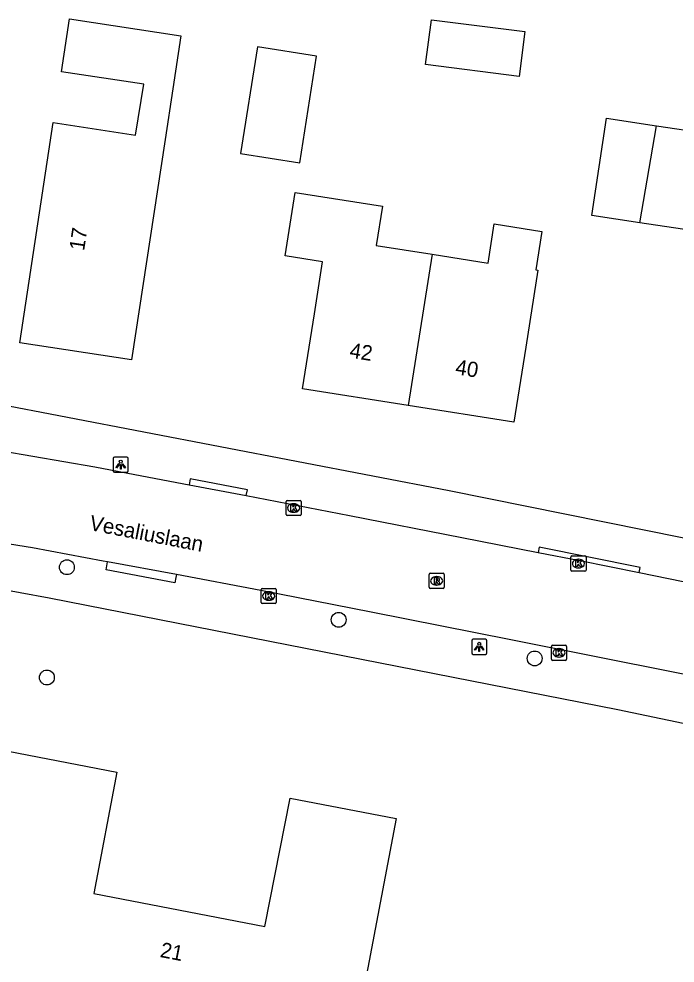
# Model space of a CAD drawing. Extents: x 161486 to 162249, y 379484 to 380829.
# Drawn here: x 161831.1 to 161874.4, y 380395.2 to 380457.4 of the extents above; entities that cross this region are included whole.
import ezdxf

# ---------------------------------------------------------------- set-up
doc = ezdxf.new("R2010")
doc.units = 0
for name, color, linetype in [('IMGEO_Boom', 7, 'Continuous'), ('IMGEO_Kolk', 7, 'Continuous'), ('IMGEO_Lichtpunt', 7, 'Continuous'), ('IMGEO_Openbare_ruimte_label', 7, 'Continuous'), ('IMGEO_Pand', 7, 'Continuous'), ('IMGEO_Pand_nummerreeks', 7, 'Continuous'), ('IMGEO_Rijbaan_lokaal_open', 7, 'Continuous'), ('IMGEO_Rioolput', 7, 'Continuous'), ('IMGEO_Voetpad_open', 7, 'Continuous')]:
    doc.layers.add(name, color=color, linetype=linetype)

msp = doc.modelspace()

# ---------------------------------------------------------------- linework, layer by layer
at = {"layer": 'IMGEO_Boom'}
for centre in [(161834.306, 380421.314), (161852.217, 380417.851), (161865.132, 380415.308), (161832.988, 380414.053)]:
    msp.add_circle(centre, 0.489, dxfattribs=at)
at = {"layer": 'IMGEO_Kolk'}
for p, q in [((161848.821, 380425.714), (161849.673, 380425.714)), ((161848.746, 380424.788), (161848.746, 380425.64)), ((161849.234, 380425.494), (161849.259, 380425.494)), ((161849.747, 380425.64), (161849.747, 380424.788)), ((161849.673, 380424.714), (161848.821, 380424.714)), ((161849.257, 380424.934), (161849.232, 380424.934)), ((161867.512, 380421.129), (161867.512, 380421.981)), ((161867.587, 380422.055), (161868.439, 380422.055)), ((161868.513, 380421.981), (161868.513, 380421.129)), ((161868, 380421.835), (161868.025, 380421.835)), ((161868.439, 380421.055), (161867.587, 380421.055)), ((161868.023, 380421.275), (161867.998, 380421.275)), ((161847.103, 380418.995), (161847.103, 380419.847)), ((161847.178, 380419.921), (161848.03, 380419.921)), ((161847.591, 380419.701), (161847.616, 380419.701)), ((161848.104, 380419.847), (161848.104, 380418.995)), ((161848.03, 380418.921), (161847.178, 380418.921)), ((161847.614, 380419.141), (161847.589, 380419.141)), ((161866.235, 380415.253), (161866.235, 380416.105)), ((161866.31, 380416.179), (161867.162, 380416.179)), ((161866.723, 380415.959), (161866.748, 380415.959)), ((161867.236, 380416.105), (161867.236, 380415.253)), ((161867.162, 380415.179), (161866.31, 380415.179)), ((161866.746, 380415.399), (161866.721, 380415.399))]:
    msp.add_line(p, q, dxfattribs=at)
for points in [[(161848.821, 380425.714), (161849.673, 380425.714)], [(161848.746, 380424.788), (161848.746, 380425.64)], [(161849.067, 380425.414), (161849.19, 380425.414), (161849.19, 380425.263), (161849.32, 380425.414), (161849.484, 380425.414), (161849.338, 380425.263), (161849.491, 380425.014), (161849.339, 380425.014), (161849.254, 380425.178), (161849.19, 380425.111), (161849.19, 380425.014), (161849.067, 380425.014), (161849.067, 380425.414)], [(161849.747, 380425.64), (161849.747, 380424.788)], [(161849.673, 380424.714), (161848.821, 380424.714)], [(161867.512, 380421.129), (161867.512, 380421.981)], [(161867.587, 380422.055), (161868.439, 380422.055)], [(161868.513, 380421.981), (161868.513, 380421.129)], [(161867.833, 380421.755), (161867.956, 380421.755), (161867.956, 380421.604), (161868.086, 380421.755), (161868.25, 380421.755), (161868.104, 380421.604), (161868.257, 380421.355), (161868.105, 380421.355), (161868.02, 380421.519), (161867.956, 380421.452), (161867.956, 380421.355), (161867.833, 380421.355), (161867.833, 380421.755)], [(161868.439, 380421.055), (161867.587, 380421.055)], [(161847.103, 380418.995), (161847.103, 380419.847)], [(161847.178, 380419.921), (161848.03, 380419.921)], [(161847.424, 380419.621), (161847.547, 380419.621), (161847.547, 380419.47), (161847.677, 380419.621), (161847.841, 380419.621), (161847.695, 380419.47), (161847.848, 380419.221), (161847.696, 380419.221), (161847.611, 380419.385), (161847.547, 380419.318), (161847.547, 380419.221), (161847.424, 380419.221), (161847.424, 380419.621)], [(161848.104, 380419.847), (161848.104, 380418.995)], [(161848.03, 380418.921), (161847.178, 380418.921)], [(161866.235, 380415.253), (161866.235, 380416.105)], [(161866.31, 380416.179), (161867.162, 380416.179)], [(161866.556, 380415.879), (161866.679, 380415.879), (161866.679, 380415.728), (161866.809, 380415.879), (161866.973, 380415.879), (161866.827, 380415.728), (161866.98, 380415.479), (161866.828, 380415.479), (161866.743, 380415.643), (161866.679, 380415.576), (161866.679, 380415.479), (161866.556, 380415.479), (161866.556, 380415.879)], [(161867.236, 380416.105), (161867.236, 380415.253)], [(161867.162, 380415.179), (161866.31, 380415.179)]]:
    msp.add_lwpolyline(points, dxfattribs=at)
for centre, start, end in [((161848.823, 380425.638), 91.55205, 178.44795), ((161848.823, 380425.638), 91.55205, 178.44795), ((161849.671, 380425.638), 1.55205, 88.44795), ((161849.671, 380425.638), 1.55205, 88.44795), ((161848.823, 380424.79), 181.55205, 268.44795), ((161848.823, 380424.79), 181.55205, 268.44795), ((161849.671, 380424.79), 271.55205, 358.44795), ((161849.671, 380424.79), 271.55205, 358.44795), ((161867.589, 380421.979), 91.55205, 178.44795), ((161867.589, 380421.979), 91.55205, 178.44795), ((161868.437, 380421.979), 1.55205, 88.44795), ((161868.437, 380421.979), 1.55205, 88.44795), ((161867.589, 380421.131), 181.55205, 268.44795), ((161867.589, 380421.131), 181.55205, 268.44795), ((161868.437, 380421.131), 271.55205, 358.44795), ((161868.437, 380421.131), 271.55205, 358.44795), ((161847.18, 380419.845), 91.55205, 178.44795), ((161847.18, 380419.845), 91.55205, 178.44795), ((161848.028, 380419.845), 1.55205, 88.44795), ((161848.028, 380419.845), 1.55205, 88.44795), ((161847.18, 380418.997), 181.55205, 268.44795), ((161847.18, 380418.997), 181.55205, 268.44795), ((161848.028, 380418.997), 271.55205, 358.44795), ((161848.028, 380418.997), 271.55205, 358.44795), ((161866.312, 380416.103), 91.55205, 178.44795), ((161866.312, 380416.103), 91.55205, 178.44795), ((161867.16, 380416.103), 1.55205, 88.44795), ((161867.16, 380416.103), 1.55205, 88.44795), ((161866.312, 380415.255), 181.55205, 268.44795), ((161866.312, 380415.255), 181.55205, 268.44795), ((161867.16, 380415.255), 271.55205, 358.44795), ((161867.16, 380415.255), 271.55205, 358.44795)]:
    msp.add_arc(centre, 0.0765, start, end, dxfattribs=at)
for centre, major_axis, ratio, start_param, end_param in [((161849.233, 380425.214), (-0.387, 0.002), 0.722429, 4.712389, 7.853982), ((161849.258, 380425.214), (-0.39, 0.002), 0.717154, 1.570796, 4.712389), ((161867.999, 380421.555), (-0.387, 0.002), 0.722429, 4.712389, 7.853982), ((161868.024, 380421.555), (-0.39, 0.002), 0.717154, 1.570796, 4.712389), ((161847.59, 380419.421), (-0.387, 0.002), 0.722429, 4.712389, 7.853982), ((161847.615, 380419.421), (-0.39, 0.002), 0.717154, 1.570796, 4.712389), ((161866.722, 380415.679), (-0.387, 0.002), 0.722429, 4.712389, 7.853982), ((161866.747, 380415.679), (-0.39, 0.002), 0.717154, 1.570796, 4.712389)]:
    msp.add_ellipse(centre, major_axis=major_axis, ratio=ratio, start_param=start_param, end_param=end_param, dxfattribs=at)
at = {"layer": 'IMGEO_Lichtpunt'}
for p, q in [((161837.358, 380428.471), (161837.358, 380427.664)), ((161837.358, 380428.471), (161837.358, 380427.664)), ((161838.26, 380428.566), (161837.452, 380428.566)), ((161838.26, 380428.566), (161837.452, 380428.566)), ((161838.354, 380427.664), (161838.354, 380428.471)), ((161838.354, 380427.664), (161838.354, 380428.471)), ((161837.452, 380427.57), (161838.26, 380427.57)), ((161837.452, 380427.57), (161838.26, 380427.57)), ((161860.98, 380416.476), (161860.98, 380415.669)), ((161860.98, 380416.476), (161860.98, 380415.669)), ((161861.882, 380416.571), (161861.074, 380416.571)), ((161861.882, 380416.571), (161861.074, 380416.571)), ((161861.976, 380415.669), (161861.976, 380416.476)), ((161861.976, 380415.669), (161861.976, 380416.476)), ((161861.074, 380415.575), (161861.882, 380415.575)), ((161861.074, 380415.575), (161861.882, 380415.575))]:
    msp.add_line(p, q, dxfattribs=at)
for points in [[(161837.732, 380428.135), (161837.771, 380428.107), (161837.583, 380427.845), (161837.545, 380427.872), (161837.732, 380428.135)], [(161837.944, 380428.107), (161837.982, 380428.134), (161838.169, 380427.872), (161838.13, 380427.844), (161837.944, 380428.107)], [(161837.834, 380428.087), (161837.881, 380428.087), (161837.881, 380427.765), (161837.834, 380427.765), (161837.834, 380428.087)], [(161861.354, 380416.14), (161861.393, 380416.112), (161861.205, 380415.85), (161861.167, 380415.877), (161861.354, 380416.14)], [(161861.456, 380416.092), (161861.503, 380416.092), (161861.503, 380415.77), (161861.456, 380415.77), (161861.456, 380416.092)], [(161861.566, 380416.112), (161861.604, 380416.139), (161861.791, 380415.877), (161861.752, 380415.849), (161861.566, 380416.112)]]:
    msp.add_lwpolyline(points, dxfattribs=at)
for centre in [(161837.857, 380428.269), (161861.479, 380416.274)]:
    msp.add_circle(centre, 0.0994, dxfattribs=at)
for centre, start, end in [((161837.452, 380428.471), 90, 180), ((161837.452, 380428.471), 90, 180), ((161838.26, 380428.471), 0, 90), ((161838.26, 380428.471), 0, 90), ((161837.452, 380427.664), 180, 270), ((161837.452, 380427.664), 180, 270), ((161838.26, 380427.664), 270, 0), ((161838.26, 380427.664), 270, 360), ((161861.074, 380416.476), 90, 180), ((161861.074, 380416.476), 90, 180), ((161861.882, 380416.476), 0, 90), ((161861.882, 380416.476), 0, 90), ((161861.074, 380415.669), 180, 270), ((161861.074, 380415.669), 180, 270), ((161861.882, 380415.669), 270, 0), ((161861.882, 380415.669), 270, 360)]:
    msp.add_arc(centre, 0.0946, start, end, dxfattribs=at)
at = {"layer": 'IMGEO_Pand'}
for points in [[(161841.285, 380452.827), (161840.776, 380449.476), (161838.573, 380434.968), (161831.208, 380436.086), (161833.411, 380450.594), (161838.839, 380449.771), (161839.386, 380453.116), (161833.958, 380453.939), (161834.487, 380457.423), (161841.814, 380456.311), (161841.285, 380452.827)], [(161864.486, 380456.598), (161864.116, 380453.64), (161857.926, 380454.413), (161858.33, 380457.368), (161864.486, 380456.598)], [(161845.753, 380448.566), (161849.653, 380447.95), (161850.762, 380454.963), (161846.862, 380455.58), (161845.753, 380448.566)], [(161872.05, 380444.001), (161868.901, 380444.47), (161869.871, 380450.877), (161873.15, 380450.388)], [(161873.15, 380450.388), (161876.428, 380449.9), (161875.458, 380443.493), (161872.05, 380444.001)], [(161872.05, 380444.001), (161873.15, 380450.388)], [(161856.799, 380431.958), (161849.837, 380433.053), (161850.614, 380437.993), (161851.153, 380441.421), (161848.684, 380441.811), (161849.344, 380445.993), (161855.093, 380445.084), (161854.688, 380442.506), (161858.366, 380441.927)], [(161858.366, 380441.927), (161862.062, 380441.346), (161862.467, 380443.921), (161865.6, 380443.429), (161865.203, 380440.905), (161865.341, 380440.883), (161864.543, 380435.803), (161863.766, 380430.863), (161856.799, 380431.958)], [(161858.366, 380441.927), (161856.799, 380431.958)], [(161852.108, 380384.288), (161846.46, 380385.364), (161847.158, 380389.029), (161838.861, 380390.68), (161837.702, 380389.37), (161838.077, 380389.039), (161836.324, 380387.057), (161833.156, 380388.535), (161833.367, 380388.988), (161831.953, 380389.648), (161832.38, 380390.563), (161826.209, 380393.444), (161828.206, 380397.72), (161830.444, 380409.213), (161837.606, 380407.818), (161836.094, 380399.825), (161847.349, 380397.657), (161849.011, 380406.112), (161856.01, 380404.779), (161852.108, 380384.288)]]:
    msp.add_lwpolyline(points, dxfattribs=at)
at = {"layer": 'IMGEO_Rijbaan_lokaal_open'}
for points in [[(161829.039, 380429.157), (161829.519, 380429.076), (161829.999, 380428.994), (161830.023, 380428.99), (161836.142, 380427.922), (161839.254, 380427.343), (161842.358, 380426.75)], [(161842.358, 380426.75), (161845.779, 380426.096), (161846.13, 380426.028)], [(161846.13, 380426.028), (161852.93, 380424.718), (161860.325, 380423.269), (161865.358, 380422.291), (161865.362, 380422.29)], [(161836.987, 380421.668), (161836.699, 380421.721), (161832.045, 380422.59), (161828.433, 380423.155), (161828.363, 380423.166), (161827.932, 380423.249)], [(161865.362, 380422.29), (161868.098, 380421.758), (161872.019, 380420.962), (161872.022, 380420.961)], [(161841.53, 380420.831), (161836.987, 380421.668)], [(161896.731, 380409.629), (161891.722, 380410.719), (161890.276, 380411.034), (161883.757, 380412.463), (161874.467, 380414.355), (161863.553, 380416.54), (161854.365, 380418.345), (161847.084, 380419.772), (161841.53, 380420.831)], [(161872.022, 380420.961), (161877.699, 380419.808), (161884.32, 380418.397), (161889.222, 380417.373), (161890.653, 380417.163)]]:
    msp.add_lwpolyline(points, dxfattribs=at)
at = {"layer": 'IMGEO_Rioolput'}
for p, q in [((161858.169, 380419.992), (161858.169, 380420.844)), ((161858.244, 380420.918), (161859.096, 380420.918)), ((161858.657, 380420.698), (161858.682, 380420.698)), ((161859.17, 380420.844), (161859.17, 380419.992)), ((161858.68, 380420.138), (161858.655, 380420.138)), ((161859.096, 380419.918), (161858.244, 380419.918))]:
    msp.add_line(p, q, dxfattribs=at)
for points in [[(161858.169, 380419.992), (161858.169, 380420.844)], [(161858.244, 380420.918), (161859.096, 380420.918)], [(161859.17, 380420.844), (161859.17, 380419.992)], [(161858.758, 380420.616), (161858.506, 380420.618), (161858.506, 380420.218)], [(161858.506, 380420.218), (161858.63, 380420.218), (161858.63, 380420.38), (161858.641, 380420.38)], [(161858.684, 380420.537), (161858.63, 380420.537), (161858.63, 380420.456)], [(161858.63, 380420.456), (161858.682, 380420.456)], [(161858.688, 380420.351), (161858.759, 380420.218), (161858.899, 380420.218), (161858.834, 380420.344)], [(161859.096, 380419.918), (161858.244, 380419.918)]]:
    msp.add_lwpolyline(points, dxfattribs=at)
for centre, radius, start, end in [((161858.246, 380420.842), 0.0765, 91.55205, 178.44795), ((161858.246, 380420.842), 0.0765, 91.55205, 178.44795), ((161859.094, 380420.842), 0.0765, 1.55205, 88.44795), ((161859.094, 380420.842), 0.0765, 1.55205, 88.44795), ((161858.64, 380420.327), 0.0533, 26.02933, 88.69889), ((161858.666, 380420.645), 0.19, 274.7715, 282.96867), ((161858.69, 380420.441), 0.0964, 77.00612, 93.18647), ((161858.704, 380420.498), 0.0378, 276.66336, 79.67722), ((161858.757, 380420.506), 0.109, 350.36119, 89.41601), ((161858.755, 380420.506), 0.112, 277.58423, 350.98172), ((161858.739, 380420.291), 0.108, 29.51342, 73.79051), ((161858.246, 380419.994), 0.0765, 181.55205, 268.44795), ((161858.246, 380419.994), 0.0765, 181.55205, 268.44795), ((161859.094, 380419.994), 0.0765, 271.55205, 358.44795), ((161859.094, 380419.994), 0.0765, 271.55205, 358.44795)]:
    msp.add_arc(centre, radius, start, end, dxfattribs=at)
for centre, major_axis, ratio, start_param, end_param in [((161858.656, 380420.418), (-0.387, 0.002), 0.722429, 4.712389, 7.853982), ((161858.681, 380420.418), (-0.39, 0.002), 0.717154, 1.570796, 4.712389)]:
    msp.add_ellipse(centre, major_axis=major_axis, ratio=ratio, start_param=start_param, end_param=end_param, dxfattribs=at)
at = {"layer": 'IMGEO_Voetpad_open'}
for points in [[(161910.18, 380403.657), (161870.617, 380411.917), (161833.133, 380419.277), (161827.383, 380420.325), (161803.575, 380424.662), (161764.511, 380431.266), (161690.732, 380442.772)], [(161829.302, 380432.17), (161859.489, 380426.367), (161890.306, 380420.151)], [(161846.13, 380426.028), (161846.208, 380426.413), (161842.435, 380427.145), (161842.358, 380426.75)], [(161872.022, 380420.961), (161872.091, 380421.307), (161865.433, 380422.643), (161865.362, 380422.29)], [(161841.53, 380420.831), (161841.494, 380420.635), (161841.431, 380420.296), (161836.89, 380421.151), (161836.961, 380421.536), (161836.987, 380421.668)]]:
    msp.add_lwpolyline(points, dxfattribs=at)

# ---------------------------------------------------------------- texts
at = {"layer": 'IMGEO_Openbare_ruimte_label'}
msp.add_text('Vesaliuslaan', height=1, rotation=348.99334, dxfattribs=at).set_placement((161835.739, 380423.771))
at = {"layer": 'IMGEO_Pand_nummerreeks'}
for s, rotation, p in [('17', 81.36575, (161835.442, 380442.121)), ('42', 351.06759, (161852.891, 380435.123)), ('40', 351.06476, (161859.862, 380434.027)), ('21', 349.09691, (161840.401, 380395.655))]:
    msp.add_text(s, height=1, rotation=rotation, dxfattribs=at).set_placement(p)

doc.saveas('drawing.dxf')
